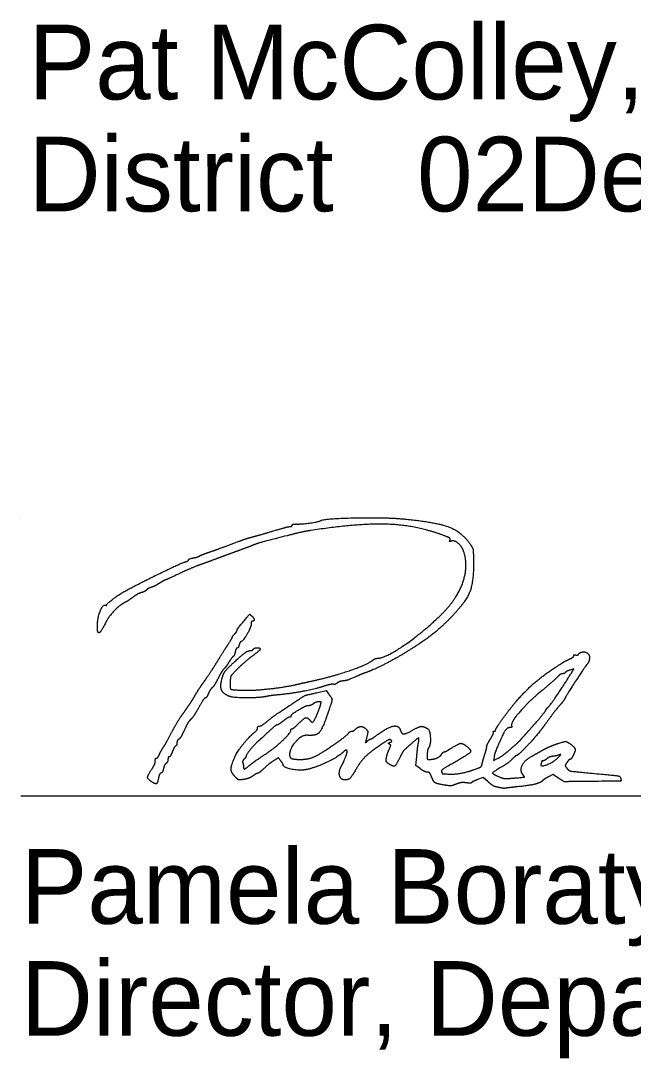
# Model space of a CAD drawing. Extents: x 0 to 34, y 0 to 22.
# Drawn here: x 24.513 to 25.662, y 6.888 to 8.834 of the extents above; entities that cross this region are included whole.
import ezdxf

# ---------------------------------------------------------------- set-up
doc = ezdxf.new("R2010")
doc.units = 0
for name, color, linetype in [('Default', 7, 'Continuous'), ('SH_Data', 7, 'Continuous'), ('SH_Text', 7, 'Continuous')]:
    doc.layers.add(name, color=color, linetype=linetype)

msp = doc.modelspace()

# ---------------------------------------------------------------- linework, layer by layer
at = {"layer": 'Default'}
for points in [[(25.5449, 7.6097), (25.5503, 7.6186), (25.543, 7.6161)], [(25.0676, 7.5735), (25.0856, 7.5776), (25.0903, 7.5714)], [(25.2626, 7.4307), (25.2542, 7.4371), (25.2557, 7.4541)], [(25.4006, 7.4527), (25.3995, 7.4462), (25.4082, 7.4507)], [(25.3895, 7.4064), (25.3804, 7.4147), (25.3698, 7.4106)], [(25.5214, 7.4134), (25.5107, 7.4202), (25.5024, 7.4157)]]:
    msp.add_lwpolyline(points, dxfattribs=at)
for points in [[(25.075, 7.8961), (25.0818, 7.9003), (25.1988, 7.9026), (25.2332, 7.8992)], [(24.9853, 7.8765), (25.0014, 7.8813), (25.0162, 7.8852), (25.0183, 7.8852)], [(25.0183, 7.8852), (25.0203, 7.8852), (25.022, 7.8863), (25.022, 7.8877)], [(25.022, 7.8877), (25.022, 7.889), (25.0261, 7.89), (25.031, 7.8899)], [(25.031, 7.8899), (25.0406, 7.8896), (25.0716, 7.894), (25.075, 7.8961)], [(25.3057, 7.8685), (25.2552, 7.8875), (25.1472, 7.8914), (25.0568, 7.8777)], [(25.2332, 7.8992), (25.2925, 7.8934), (25.34, 7.8751), (25.3558, 7.852)], [(24.9224, 7.8575), (24.9303, 7.8605), (24.9411, 7.864), (24.9464, 7.8654)], [(24.9464, 7.8654), (24.9517, 7.8667), (24.9692, 7.8718), (24.9853, 7.8765)], [(25.0124, 7.868), (24.9614, 7.8548), (24.9571, 7.8535), (24.9464, 7.8492)], [(25.0568, 7.8777), (25.0476, 7.8763), (25.0276, 7.8719), (25.0124, 7.868)], [(25.318, 7.8598), (25.319, 7.8623), (25.3156, 7.8648), (25.3057, 7.8685)], [(24.866, 7.837), (24.8807, 7.842), (24.8872, 7.8444), (24.9224, 7.8575)], [(24.9464, 7.8492), (24.9438, 7.8481), (24.9335, 7.8443), (24.9236, 7.8407)], [(25.3204, 7.8578), (25.3178, 7.8568), (25.3171, 7.8574), (25.318, 7.8598)], [(25.3438, 7.8378), (25.3406, 7.8476), (25.3261, 7.8599), (25.3204, 7.8578)], [(25.3558, 7.852), (25.3608, 7.8448), (25.3617, 7.8404), (25.362, 7.8226)], [(24.8222, 7.8191), (24.8252, 7.82), (24.8276, 7.8216), (24.8276, 7.8227)], [(24.8276, 7.8227), (24.8276, 7.8238), (24.8317, 7.8254), (24.8366, 7.8263)], [(24.8366, 7.8263), (24.8416, 7.8272), (24.8467, 7.8288), (24.848, 7.8298)], [(24.848, 7.8298), (24.8493, 7.8308), (24.8574, 7.834), (24.866, 7.837)], [(24.89, 7.8283), (24.8814, 7.8251), (24.8652, 7.8191), (24.854, 7.8152)], [(24.9236, 7.8407), (24.9137, 7.8371), (24.8986, 7.8315), (24.89, 7.8283)], [(25.2983, 7.7167), (25.3293, 7.7461), (25.3531, 7.8096), (25.3438, 7.8378)], [(25.362, 7.8226), (25.3628, 7.7818), (25.3467, 7.7421), (25.3172, 7.7122)], [(24.71, 7.7648), (24.7402, 7.781), (24.8138, 7.8167), (24.8222, 7.8191)], [(24.854, 7.8152), (24.8428, 7.8112), (24.8225, 7.8026), (24.8088, 7.7961)], [(24.7829, 7.7844), (24.7824, 7.7844), (24.7779, 7.7818), (24.773, 7.7787)], [(24.8088, 7.7961), (24.7951, 7.7897), (24.7835, 7.7844), (24.7829, 7.7844)], [(24.674, 7.7382), (24.674, 7.7403), (24.6994, 7.7591), (24.71, 7.7648)], [(24.749, 7.7661), (24.7472, 7.7643), (24.7428, 7.7621), (24.7393, 7.7612)], [(24.7581, 7.7712), (24.7549, 7.7702), (24.7508, 7.7679), (24.749, 7.7661)], [(24.773, 7.7787), (24.7681, 7.7756), (24.7614, 7.7722), (24.7581, 7.7712)], [(24.7244, 7.7531), (24.7198, 7.7496), (24.7127, 7.7449), (24.7085, 7.7428)], [(24.7393, 7.7612), (24.7357, 7.7604), (24.729, 7.7567), (24.7244, 7.7531)], [(24.6569, 7.7003), (24.657, 7.7135), (24.6676, 7.7401), (24.6717, 7.7375)], [(24.6717, 7.7375), (24.673, 7.7367), (24.674, 7.737), (24.674, 7.7382)], [(24.7085, 7.7428), (24.6981, 7.7375), (24.6782, 7.7166), (24.672, 7.7045)], [(24.9242, 7.6992), (24.9428, 7.7214), (24.9421, 7.7208), (24.9462, 7.7174)], [(24.9476, 7.7076), (24.9463, 7.7076), (24.9452, 7.7053), (24.9452, 7.7025)], [(24.9462, 7.7174), (24.9504, 7.7138), (24.9514, 7.7076), (24.9476, 7.7076)], [(25.1816, 7.638), (25.1957, 7.638), (25.2638, 7.6839), (25.2983, 7.7167)], [(25.3172, 7.7122), (25.2987, 7.6933), (25.2663, 7.6684), (25.2358, 7.6496)], [(24.6582, 7.6866), (24.6574, 7.6874), (24.6568, 7.6935), (24.6569, 7.7003)], [(24.672, 7.7045), (24.6654, 7.6916), (24.6601, 7.6847), (24.6582, 7.6866)], [(24.914, 7.6836), (24.9167, 7.6862), (24.9188, 7.6894), (24.9188, 7.6906)], [(24.9188, 7.6906), (24.9188, 7.6918), (24.9213, 7.6957), (24.9242, 7.6992)], [(24.9452, 7.7025), (24.9452, 7.6969), (24.9293, 7.6692), (24.9261, 7.6692)], [(24.9013, 7.6631), (24.9068, 7.6717), (24.9109, 7.6788), (24.9103, 7.6788)], [(24.9103, 7.6788), (24.9097, 7.6788), (24.9114, 7.6809), (24.914, 7.6836)], [(24.9261, 7.6692), (24.925, 7.6692), (24.9235, 7.6665), (24.9226, 7.6632)], [(24.8792, 7.6281), (24.8858, 7.6387), (24.8957, 7.6545), (24.9013, 7.6631)], [(24.9104, 7.6282), (24.9261, 7.6428), (24.9389, 7.6524), (24.9428, 7.6524)], [(24.9152, 7.65), (24.9144, 7.6461), (24.9126, 7.6422), (24.9113, 7.6414)], [(24.919, 7.6572), (24.9178, 7.6572), (24.9161, 7.6539), (24.9152, 7.65)], [(24.9226, 7.6632), (24.9218, 7.6599), (24.9202, 7.6572), (24.919, 7.6572)], [(24.9428, 7.6524), (24.9453, 7.6524), (24.948, 7.6535), (24.9488, 7.6548)], [(24.962, 7.6551), (24.962, 7.654), (24.9553, 7.6481), (24.947, 7.642)], [(24.9488, 7.6548), (24.9506, 7.6577), (24.962, 7.658), (24.962, 7.6551)], [(25.2358, 7.6496), (25.2166, 7.6377), (25.1753, 7.6167), (25.1612, 7.6116)], [(25.5597, 7.6465), (25.5613, 7.6484), (25.565, 7.65), (25.5679, 7.65)], [(25.5679, 7.65), (25.5774, 7.65), (25.5811, 7.6339), (25.5737, 7.625)], [(24.8575, 7.5952), (24.8628, 7.6026), (24.8726, 7.6175), (24.8792, 7.6281)], [(24.8891, 7.5936), (24.8918, 7.6066), (24.898, 7.6166), (24.9104, 7.6282)], [(24.9029, 7.63), (24.8995, 7.6245), (24.8953, 7.6189), (24.8937, 7.6175)], [(24.9113, 7.6414), (24.9101, 7.6406), (24.9063, 7.6355), (24.9029, 7.63)], [(24.947, 7.642), (24.9388, 7.6359), (24.9263, 7.6251), (24.9192, 7.6179)], [(25.0616, 7.596), (25.0986, 7.6042), (25.1648, 7.6271), (25.1734, 7.6347)], [(25.1734, 7.6347), (25.1755, 7.6365), (25.1792, 7.638), (25.1816, 7.638)], [(25.5132, 7.6196), (25.5322, 7.6318), (25.534, 7.6329), (25.5422, 7.6366)], [(25.5422, 7.6366), (25.5465, 7.6385), (25.55, 7.6414), (25.55, 7.6429)], [(25.55, 7.6429), (25.55, 7.6444), (25.5516, 7.6451), (25.5534, 7.6444)], [(25.5534, 7.6444), (25.5553, 7.6436), (25.5582, 7.6446), (25.5597, 7.6465)], [(24.8937, 7.6175), (24.892, 7.6162), (24.8874, 7.6086), (24.8833, 7.6006)], [(24.9192, 7.6179), (24.9085, 7.6069), (24.9063, 7.6033), (24.9058, 7.595)], [(25.1612, 7.6116), (25.1566, 7.61), (25.1496, 7.6072), (25.1456, 7.6054)], [(25.4186, 7.5271), (25.4409, 7.5579), (25.4859, 7.6019), (25.5132, 7.6196)], [(25.5021, 7.5468), (25.505, 7.5487), (25.5332, 7.5902), (25.5449, 7.6097)], [(25.529, 7.6092), (25.5268, 7.6092), (25.5228, 7.6067), (25.5201, 7.6038)], [(25.5343, 7.6113), (25.5335, 7.6101), (25.5311, 7.6092), (25.529, 7.6092)], [(25.5737, 7.625), (25.5696, 7.6199), (25.5367, 7.5695), (25.5336, 7.5633)], [(25.543, 7.6161), (25.5389, 7.6147), (25.535, 7.6125), (25.5343, 7.6113)], [(24.8407, 7.5696), (24.8446, 7.5762), (24.8521, 7.5877), (24.8575, 7.5952)], [(24.8833, 7.6006), (24.8793, 7.5926), (24.8742, 7.5846), (24.8721, 7.5828)], [(24.9044, 7.5667), (24.894, 7.5706), (24.8869, 7.5831), (24.8891, 7.5936)], [(24.9058, 7.595), (24.905, 7.5816), (24.909, 7.5787), (24.9296, 7.5782)], [(24.9296, 7.5782), (24.9489, 7.5776), (25.0067, 7.5837), (25.028, 7.5885)], [(25.028, 7.5885), (25.0359, 7.5903), (25.0511, 7.5937), (25.0616, 7.596)], [(25.0994, 7.5893), (25.0978, 7.5899), (25.0897, 7.5882), (25.0814, 7.5856)], [(25.1062, 7.5915), (25.1041, 7.5897), (25.1011, 7.5887), (25.0994, 7.5893)], [(25.117, 7.5956), (25.1131, 7.5951), (25.1083, 7.5933), (25.1062, 7.5915)], [(25.1456, 7.6054), (25.1285, 7.598), (25.1236, 7.5963), (25.117, 7.5956)], [(25.5201, 7.6038), (25.5174, 7.6008), (25.505, 7.5897), (25.4924, 7.5792)], [(24.8277, 7.5489), (24.831, 7.5537), (24.8369, 7.563), (24.8407, 7.5696)], [(24.8648, 7.5716), (24.863, 7.5672), (24.8604, 7.5636), (24.8591, 7.5636)], [(24.8721, 7.5828), (24.8699, 7.581), (24.8666, 7.576), (24.8648, 7.5716)], [(24.9961, 7.5695), (24.9877, 7.5687), (24.9785, 7.5675), (24.9757, 7.5669)], [(25.0814, 7.5856), (25.065, 7.5803), (25.0199, 7.5718), (24.9961, 7.5695)], [(25.0136, 7.5471), (25.0453, 7.5681), (25.0467, 7.5688), (25.0676, 7.5735)], [(25.0903, 7.5714), (25.0969, 7.5627), (25.0967, 7.5578), (25.089, 7.5352)], [(25.4924, 7.5792), (25.4728, 7.5627), (25.4611, 7.5513), (25.4444, 7.5324)], [(24.8591, 7.5636), (24.8578, 7.5636), (24.8524, 7.5557), (24.8471, 7.546)], [(24.9757, 7.5669), (24.9619, 7.5638), (24.9125, 7.5637), (24.9044, 7.5667)], [(25.0618, 7.5527), (25.0592, 7.5508), (25.0553, 7.5492), (25.053, 7.5492)], [(25.0603, 7.518), (25.0621, 7.518), (25.0718, 7.5391), (25.075, 7.5498)], [(25.0717, 7.5563), (25.0688, 7.5563), (25.0643, 7.5546), (25.0618, 7.5527)], [(25.075, 7.5498), (25.0766, 7.5556), (25.0762, 7.5564), (25.0717, 7.5563)], [(25.5249, 7.5512), (25.5219, 7.5479), (25.513, 7.5366), (25.5051, 7.526)], [(25.5336, 7.5633), (25.5318, 7.5598), (25.5279, 7.5544), (25.5249, 7.5512)], [(24.8142, 7.5297), (24.8183, 7.5355), (24.8244, 7.5442), (24.8277, 7.5489)], [(24.8471, 7.546), (24.8417, 7.5364), (24.8351, 7.5264), (24.8322, 7.5238)], [(24.9744, 7.5192), (24.9881, 7.5303), (24.9862, 7.5289), (25.0136, 7.5471)], [(25.0433, 7.546), (25.0289, 7.5381), (25.0196, 7.5317), (25.0196, 7.5297)], [(25.053, 7.5492), (25.0508, 7.5492), (25.0464, 7.5478), (25.0433, 7.546)], [(25.089, 7.5352), (25.0788, 7.5053), (25.0668, 7.4923), (25.0508, 7.4936)], [(25.4444, 7.5324), (25.4386, 7.5258), (25.4323, 7.5129), (25.4338, 7.5106)], [(25.4669, 7.5038), (25.4823, 7.5209), (25.4958, 7.5373), (25.4982, 7.5416)], [(25.4982, 7.5416), (25.4994, 7.5438), (25.5012, 7.5461), (25.5021, 7.5468)], [(24.7953, 7.4976), (24.8016, 7.5095), (24.8101, 7.5239), (24.8142, 7.5297)], [(24.8322, 7.5238), (24.8294, 7.5213), (24.8238, 7.5122), (24.8199, 7.5036)], [(24.9572, 7.5073), (24.9572, 7.5092), (24.9587, 7.5108), (24.9606, 7.5108)], [(24.9941, 7.5132), (24.9922, 7.5131), (24.9837, 7.5059), (24.9584, 7.4826)], [(24.9606, 7.5108), (24.9625, 7.5108), (24.9687, 7.5146), (24.9744, 7.5192)], [(25.0052, 7.5204), (25.0002, 7.5164), (24.9952, 7.5132), (24.9941, 7.5132)], [(25.017, 7.5276), (25.0155, 7.5276), (25.0102, 7.5243), (25.0052, 7.5204)], [(25.0196, 7.5297), (25.0196, 7.5285), (25.0184, 7.5276), (25.017, 7.5276)], [(25.022, 7.506), (25.0233, 7.506), (25.0287, 7.5103), (25.034, 7.5156)], [(25.034, 7.5156), (25.0442, 7.5257), (25.0507, 7.5275), (25.0556, 7.5216)], [(25.0556, 7.5216), (25.0573, 7.5196), (25.0594, 7.518), (25.0603, 7.518)], [(25.1788, 7.4925), (25.199, 7.5077), (25.2217, 7.5133), (25.2247, 7.5038)], [(25.2485, 7.5035), (25.2605, 7.5101), (25.2677, 7.5108), (25.2759, 7.5062)], [(25.4036, 7.5037), (25.4036, 7.5052), (25.4104, 7.5157), (25.4186, 7.5271)], [(25.4338, 7.5106), (25.4345, 7.5094), (25.4335, 7.5084), (25.4315, 7.5084)], [(25.5051, 7.526), (25.4972, 7.5153), (25.4896, 7.5051), (25.4881, 7.5033)], [(24.7798, 7.47), (24.782, 7.4733), (24.789, 7.4857), (24.7953, 7.4976)], [(24.8199, 7.5036), (24.816, 7.495), (24.8112, 7.4871), (24.8094, 7.4861)], [(24.9137, 7.4513), (24.9182, 7.4618), (24.9414, 7.4912), (24.9518, 7.4995)], [(24.9518, 7.4995), (24.9548, 7.502), (24.9572, 7.5055), (24.9572, 7.5073)], [(24.9736, 7.4594), (24.9891, 7.4698), (25.0196, 7.4986), (25.0196, 7.5028)], [(25.0508, 7.4936), (25.0404, 7.4945), (25.0172, 7.4691), (25.0172, 7.4569)], [(25.0196, 7.5028), (25.0196, 7.5046), (25.0207, 7.506), (25.022, 7.506)], [(25.0856, 7.4663), (25.1042, 7.4787), (25.1266, 7.4953), (25.1283, 7.4981)], [(25.1283, 7.4981), (25.1294, 7.4998), (25.1318, 7.5012), (25.1336, 7.5012)], [(25.1336, 7.5012), (25.1354, 7.5012), (25.1386, 7.5029), (25.1408, 7.5051)], [(25.1408, 7.5051), (25.1458, 7.51), (25.1557, 7.5101), (25.1607, 7.5052)], [(25.1607, 7.5052), (25.1638, 7.502), (25.1641, 7.4995), (25.162, 7.4904)], [(25.1694, 7.4868), (25.1703, 7.4868), (25.1746, 7.4893), (25.1788, 7.4925)], [(25.2247, 7.5038), (25.2271, 7.4962), (25.2352, 7.4961), (25.2485, 7.5035)], [(25.2759, 7.5062), (25.2803, 7.5038), (25.282, 7.4757), (25.2781, 7.4706)], [(25.3939, 7.4869), (25.3977, 7.4932), (25.4002, 7.499), (25.3995, 7.4997)], [(25.3995, 7.4997), (25.3987, 7.5005), (25.3993, 7.5012), (25.4008, 7.5012)], [(25.4008, 7.5012), (25.4024, 7.5012), (25.4036, 7.5023), (25.4036, 7.5037)], [(25.4315, 7.5084), (25.4252, 7.5084), (25.4156, 7.4932), (25.4036, 7.464)], [(25.4513, 7.4863), (25.4545, 7.4899), (25.4615, 7.4977), (25.4669, 7.5038)], [(25.4881, 7.5033), (25.4748, 7.4869), (25.4703, 7.4817), (25.4584, 7.4695)], [(24.8035, 7.4735), (24.8021, 7.4727), (24.7993, 7.4677), (24.7973, 7.4626)], [(24.806, 7.4796), (24.806, 7.4771), (24.8049, 7.4744), (24.8035, 7.4735)], [(24.8094, 7.4861), (24.8075, 7.485), (24.806, 7.4821), (24.806, 7.4796)], [(24.9584, 7.4826), (24.9493, 7.4743), (24.9356, 7.4572), (24.9356, 7.4542)], [(25.1873, 7.4752), (25.1675, 7.4618), (25.1503, 7.4448), (25.142, 7.4304)], [(25.162, 7.4904), (25.1596, 7.4801), (25.1597, 7.4796), (25.1635, 7.4831)], [(25.1635, 7.4831), (25.1658, 7.4851), (25.1684, 7.4868), (25.1694, 7.4868)], [(25.2075, 7.4847), (25.2057, 7.4865), (25.1998, 7.4837), (25.1873, 7.4752)], [(25.2046, 7.4771), (25.2024, 7.4784), (25.2027, 7.4793), (25.2058, 7.4805)], [(25.2039, 7.4672), (25.2068, 7.4735), (25.2069, 7.4756), (25.2046, 7.4771)], [(25.2058, 7.4805), (25.2088, 7.4817), (25.2093, 7.4829), (25.2075, 7.4847)], [(25.2486, 7.4806), (25.2326, 7.4666), (25.2289, 7.4622), (25.2234, 7.4508)], [(25.2587, 7.479), (25.2605, 7.4884), (25.2579, 7.4888), (25.2486, 7.4806)], [(25.2557, 7.4541), (25.2565, 7.4635), (25.2578, 7.4747), (25.2587, 7.479)], [(25.3494, 7.4729), (25.3591, 7.4653), (25.3523, 7.4574), (25.3207, 7.4397)], [(25.3212, 7.47), (25.3342, 7.4782), (25.3418, 7.479), (25.3494, 7.4729)], [(25.3833, 7.458), (25.3853, 7.4639), (25.3868, 7.4703), (25.3868, 7.4721)], [(25.3868, 7.4721), (25.3868, 7.4739), (25.39, 7.4806), (25.3939, 7.4869)], [(25.4312, 7.4675), (25.4391, 7.4743), (25.4482, 7.4828), (25.4513, 7.4863)], [(25.4912, 7.4655), (25.4991, 7.47), (25.5123, 7.4757), (25.5205, 7.4782)], [(25.5205, 7.4782), (25.5346, 7.4824), (25.5358, 7.4824), (25.5416, 7.4786)], [(25.5416, 7.4786), (25.5512, 7.4723), (25.5536, 7.4649), (25.549, 7.4559)], [(24.7677, 7.4508), (24.769, 7.4508), (24.7714, 7.4537), (24.773, 7.4574)], [(24.773, 7.4574), (24.7745, 7.461), (24.7776, 7.4667), (24.7798, 7.47)], [(24.7914, 7.4532), (24.7902, 7.4532), (24.7892, 7.4511), (24.7892, 7.4487)], [(24.7973, 7.4626), (24.7952, 7.4574), (24.7925, 7.4532), (24.7914, 7.4532)], [(24.9356, 7.4542), (24.9356, 7.4535), (24.9339, 7.4511), (24.9319, 7.4491)], [(24.942, 7.4371), (24.9496, 7.4432), (24.9548, 7.4469), (24.9736, 7.4594)], [(25.0172, 7.4569), (25.0172, 7.4517), (25.025, 7.4484), (25.0372, 7.4484)], [(25.0372, 7.4484), (25.0502, 7.4484), (25.0693, 7.4554), (25.0856, 7.4663)], [(25.1176, 7.4621), (25.108, 7.453), (25.0693, 7.4342), (25.0508, 7.4298)], [(25.1146, 7.4364), (25.1188, 7.444), (25.1252, 7.4603), (25.1252, 7.4631)], [(25.1252, 7.4631), (25.1252, 7.4661), (25.1213, 7.4656), (25.1176, 7.4621)], [(25.1988, 7.4516), (25.1996, 7.4558), (25.2019, 7.4628), (25.2039, 7.4672)], [(25.2752, 7.458), (25.2747, 7.4504), (25.2754, 7.4484), (25.2785, 7.4484)], [(25.2781, 7.4706), (25.2768, 7.4689), (25.2755, 7.4632), (25.2752, 7.458)], [(25.2785, 7.4484), (25.2868, 7.4484), (25.2988, 7.4532), (25.3021, 7.4579)], [(25.3021, 7.4579), (25.304, 7.4606), (25.3065, 7.4628), (25.3077, 7.4628)], [(25.3077, 7.4628), (25.3089, 7.4628), (25.315, 7.466), (25.3212, 7.47)], [(25.3785, 7.4409), (25.3792, 7.4444), (25.3814, 7.452), (25.3833, 7.458)], [(25.4036, 7.464), (25.4025, 7.4613), (25.4011, 7.4563), (25.4006, 7.4527)], [(25.4082, 7.4507), (25.4129, 7.4531), (25.4233, 7.4607), (25.4312, 7.4675)], [(25.4428, 7.4556), (25.4417, 7.4556), (25.4379, 7.4524), (25.4342, 7.4486)], [(25.4584, 7.4695), (25.4509, 7.4619), (25.4439, 7.4556), (25.4428, 7.4556)], [(25.4546, 7.4201), (25.4485, 7.4275), (25.4583, 7.4473), (25.4717, 7.4545)], [(25.4717, 7.4545), (25.4745, 7.456), (25.4833, 7.461), (25.4912, 7.4655)], [(25.5106, 7.4541), (25.5068, 7.4536), (25.5018, 7.4516), (25.4996, 7.4496)], [(25.5224, 7.4568), (25.5198, 7.4558), (25.5145, 7.4546), (25.5106, 7.4541)], [(25.52, 7.4513), (25.5255, 7.4569), (25.5261, 7.4582), (25.5224, 7.4568)], [(25.549, 7.4559), (25.5469, 7.4518), (25.5442, 7.4484), (25.543, 7.4484)], [(24.7594, 7.4309), (24.7626, 7.4356), (24.7652, 7.442), (24.7652, 7.4451)], [(24.7652, 7.4451), (24.7652, 7.4482), (24.7663, 7.4508), (24.7677, 7.4508)], [(24.7858, 7.4413), (24.7839, 7.4397), (24.7816, 7.4352), (24.7808, 7.4312)], [(24.7892, 7.4487), (24.7892, 7.4462), (24.7877, 7.4429), (24.7858, 7.4413)], [(24.9154, 7.4156), (24.9078, 7.4232), (24.9072, 7.436), (24.9137, 7.4513)], [(24.9319, 7.4491), (24.9298, 7.447), (24.9287, 7.4438), (24.9295, 7.4419)], [(24.9295, 7.4419), (24.9302, 7.4399), (24.9308, 7.4368), (24.9308, 7.435)], [(24.9308, 7.435), (24.9308, 7.4301), (24.9342, 7.4308), (24.942, 7.4371)], [(24.9893, 7.4472), (24.9811, 7.4418), (24.9786, 7.4398), (24.9673, 7.4298)], [(25.0006, 7.4458), (24.9962, 7.4516), (24.9961, 7.4516), (24.9893, 7.4472)], [(25.0052, 7.4384), (25.0051, 7.4393), (25.0031, 7.4426), (25.0006, 7.4458)], [(25.0508, 7.4298), (25.038, 7.4267), (25.0054, 7.4329), (25.0052, 7.4384)], [(25.1214, 7.41), (25.113, 7.41), (25.1089, 7.4258), (25.1146, 7.4364)], [(25.2034, 7.4401), (25.1985, 7.4433), (25.1977, 7.4453), (25.1988, 7.4516)], [(25.2234, 7.4508), (25.2167, 7.4371), (25.2119, 7.4345), (25.2034, 7.4401)], [(25.3207, 7.4397), (25.3075, 7.4323), (25.3012, 7.4274), (25.3021, 7.4253)], [(25.3659, 7.4303), (25.3747, 7.4336), (25.3776, 7.4361), (25.3785, 7.4409)], [(25.4162, 7.435), (25.3983, 7.4246), (25.3973, 7.4213), (25.4102, 7.4158)], [(25.4342, 7.4486), (25.4306, 7.4448), (25.4225, 7.4387), (25.4162, 7.435)], [(25.4886, 7.4402), (25.4861, 7.4337), (25.5116, 7.4427), (25.52, 7.4513)], [(25.49, 7.445), (25.49, 7.4444), (25.4894, 7.4423), (25.4886, 7.4402)], [(25.4928, 7.446), (25.4913, 7.446), (25.49, 7.4455), (25.49, 7.445)], [(25.4996, 7.4496), (25.4974, 7.4476), (25.4944, 7.446), (25.4928, 7.446)], [(25.5372, 7.4426), (25.5337, 7.4372), (25.5337, 7.4363), (25.5375, 7.4316)], [(25.543, 7.4484), (25.5419, 7.4484), (25.5393, 7.4458), (25.5372, 7.4426)], [(24.7577, 7.4072), (24.7507, 7.412), (24.7512, 7.4188), (24.7594, 7.4309)], [(24.7714, 7.4136), (24.7696, 7.4039), (24.7654, 7.4019), (24.7577, 7.4072)], [(24.776, 7.4228), (24.7743, 7.4222), (24.7722, 7.418), (24.7714, 7.4136)], [(24.7808, 7.4312), (24.7799, 7.4273), (24.7778, 7.4235), (24.776, 7.4228)], [(24.9316, 7.411), (24.9229, 7.4096), (24.9207, 7.4102), (24.9154, 7.4156)], [(24.9481, 7.4172), (24.9445, 7.4146), (24.9371, 7.4118), (24.9316, 7.411)], [(24.9566, 7.422), (24.9555, 7.422), (24.9517, 7.4198), (24.9481, 7.4172)], [(24.9673, 7.4298), (24.9625, 7.4255), (24.9577, 7.422), (24.9566, 7.422)], [(25.142, 7.4304), (25.1338, 7.4163), (25.1275, 7.41), (25.1214, 7.41)], [(25.2756, 7.4244), (25.273, 7.4244), (25.2671, 7.4272), (25.2626, 7.4307)], [(25.2831, 7.4166), (25.2812, 7.4217), (25.2787, 7.4244), (25.2756, 7.4244)], [(25.3084, 7.4001), (25.2934, 7.4025), (25.2866, 7.4069), (25.2831, 7.4166)], [(25.3021, 7.4253), (25.3034, 7.4218), (25.3041, 7.4216), (25.316, 7.4209)], [(25.316, 7.4209), (25.3265, 7.4203), (25.3527, 7.4252), (25.3659, 7.4303)], [(25.4102, 7.4158), (25.4171, 7.4129), (25.4235, 7.4123), (25.437, 7.4134)], [(25.437, 7.4134), (25.4566, 7.4149), (25.4583, 7.4156), (25.4546, 7.4201)], [(25.5024, 7.4157), (25.4977, 7.4132), (25.4925, 7.4097), (25.4906, 7.4078)], [(25.568, 7.407), (25.5323, 7.4066), (25.5319, 7.4066), (25.5214, 7.4134)], [(25.5375, 7.4316), (25.5412, 7.4271), (25.5461, 7.4261), (25.58, 7.4229)], [(25.58, 7.4229), (25.6291, 7.4184), (25.6374, 7.4169), (25.6383, 7.4121)], [(25.3296, 7.402), (25.3226, 7.3992), (25.317, 7.3987), (25.3084, 7.4001)], [(25.3484, 7.4045), (25.3427, 7.4053), (25.3354, 7.4043), (25.3296, 7.402)], [(25.3585, 7.4049), (25.3581, 7.404), (25.3536, 7.4038), (25.3484, 7.4045)], [(25.3698, 7.4106), (25.364, 7.4083), (25.3589, 7.4058), (25.3585, 7.4049)], [(25.4042, 7.3969), (25.4012, 7.3976), (25.3946, 7.4018), (25.3895, 7.4064)], [(25.4144, 7.3948), (25.4118, 7.3953), (25.4072, 7.3963), (25.4042, 7.3969)], [(25.4228, 7.3945), (25.4208, 7.3941), (25.4171, 7.3942), (25.4144, 7.3948)], [(25.442, 7.3968), (25.4334, 7.396), (25.4248, 7.3949), (25.4228, 7.3945)], [(25.4906, 7.4078), (25.4869, 7.4041), (25.4654, 7.3992), (25.442, 7.3968)], [(25.6383, 7.4121), (25.6391, 7.4078), (25.6372, 7.4077), (25.568, 7.407)]]:
    msp.add_open_spline(points, degree=2, dxfattribs=at)
at = {"layer": 'SH_Data'}
for p, q in [((24.5131, 7.9025), (24.5131, 7.9025)), ((24.5131, 7.3802), (28.0131, 7.3802))]:
    msp.add_line(p, q, dxfattribs=at)

# ---------------------------------------------------------------- texts
at = {"layer": 'SH_Text'}
for s, p in [('Pat McColley, P.E., S.I.', (24.5279, 8.6862)), ('District       Deputy Director', (24.5279, 8.4762)), ('              02', (24.5279, 8.4762)), ('Pamela Boratyn', (24.5131, 7.1402)), ('Director, Department of Transportation', (24.5131, 6.9302))]:
    msp.add_text(s, height=0.14, dxfattribs=at).set_placement(p)

doc.saveas('drawing.dxf')
